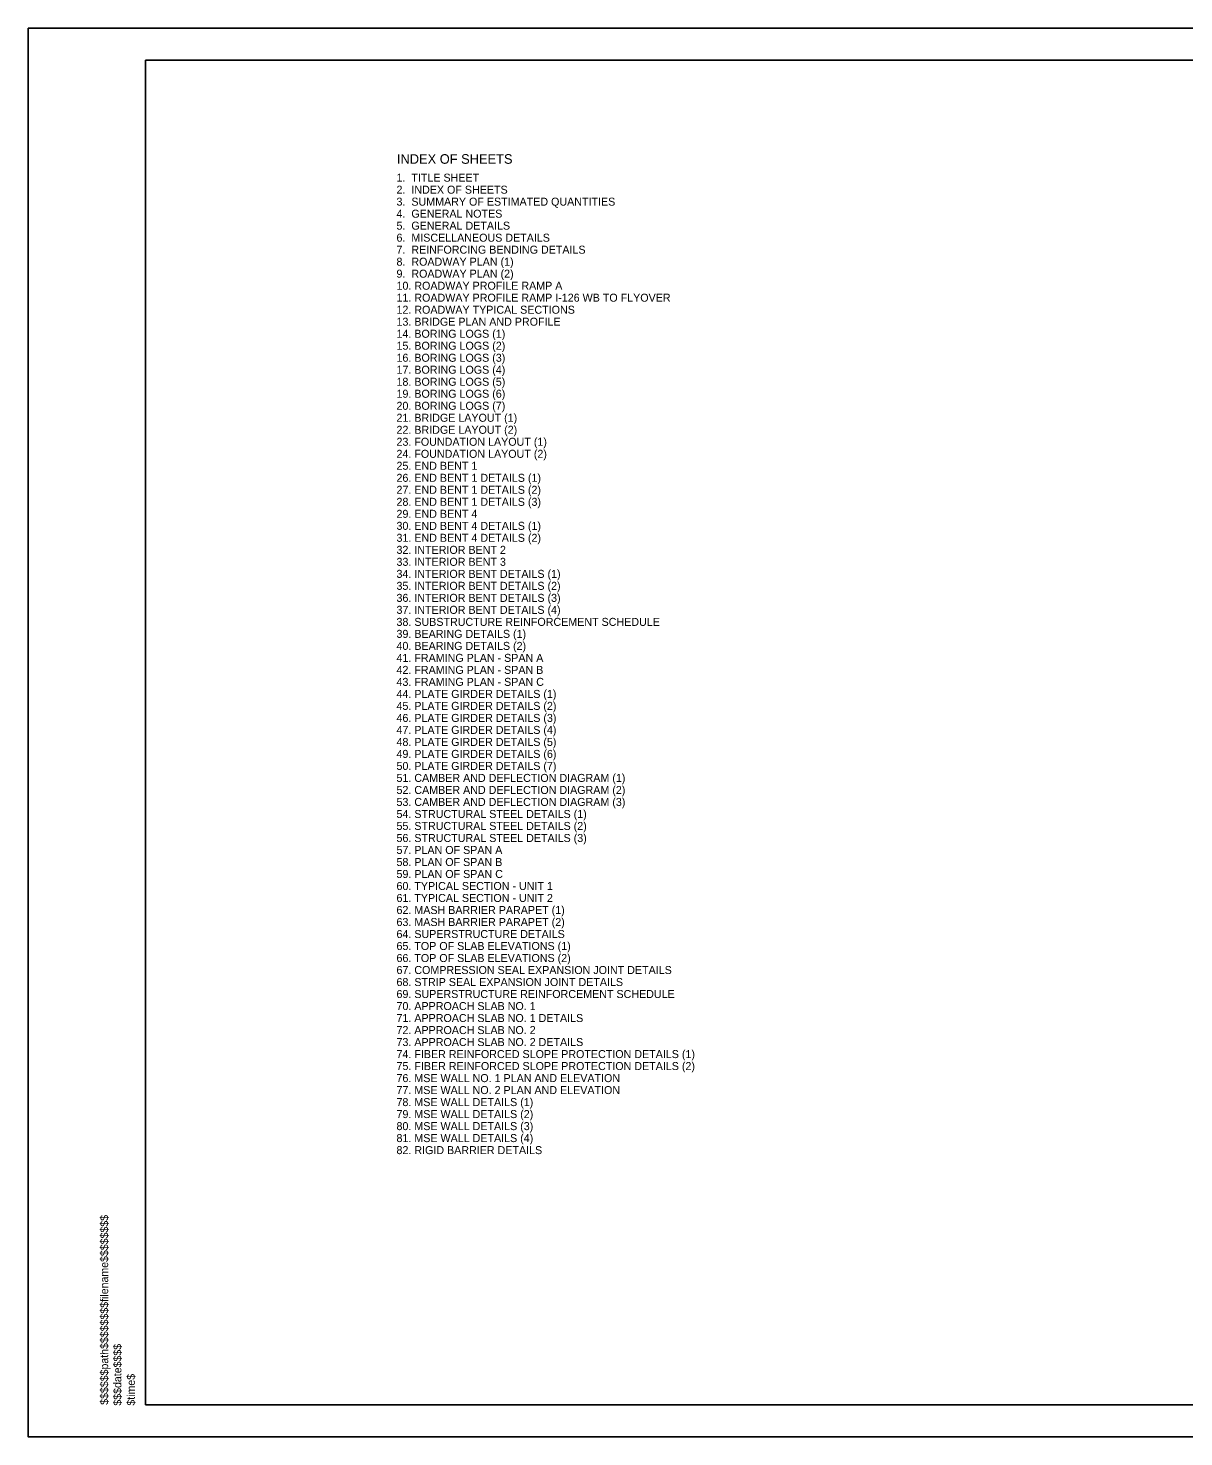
# Model space of a CAD drawing. Extents: x -125.5 to -89.4, y -5.1 to 16.9.
# Drawn here: x -125.53 to -107.48, y -5.07 to 16.93 of the extents above; entities that cross this region are included whole.
import ezdxf

# ---------------------------------------------------------------- set-up
doc = ezdxf.new("R2010")
doc.units = 0
for name, color, linetype in [('BR_AUTO DIMENSION', 7, 'Continuous'), ('BR_BORDER LINES', 7, 'Continuous'), ('BR_TEXT', 7, 'Continuous'), ('Level 31', 7, 'Continuous'), ('RD_SHT_ID', 7, 'Continuous')]:
    doc.layers.add(name, color=color, linetype=linetype)

msp = doc.modelspace()

# ---------------------------------------------------------------- linework, layer by layer
at = {"layer": 'BR_BORDER LINES'}
for p, q in [((-90.033, 16.434), (-123.699, 16.434)), ((-123.699, -4.566), (-123.699, 16.434)), ((-123.699, -4.566), (-90.033, -4.566))]:
    msp.add_line(p, q, dxfattribs=at)
at = {"layer": 'Level 31'}
msp.add_line((-89.533, 16.934), (-125.533, 16.934), dxfattribs=at)
msp.add_lwpolyline([(-125.533, 16.934), (-125.533, -5.066), (-89.533, -5.066), (-89.533, 16.934)], dxfattribs=at)

# ---------------------------------------------------------------- texts
at = {"layer": 'BR_AUTO DIMENSION'}
msp.add_text('INDEX OF SHEETS', height=0.15, dxfattribs=at).set_placement((-119.772, 14.816))
at = {"layer": 'BR_TEXT'}
for s, p in [('1.  TITLE SHEET', (-119.779, 14.537)), ('2.  INDEX OF SHEETS', (-119.779, 14.349)), ('4.  GENERAL NOTES', (-119.779, 13.974)), ('3.  SUMMARY OF ESTIMATED QUANTITIES', (-119.779, 14.162)), ('5.  GENERAL DETAILS', (-119.779, 13.787)), ('6.  MISCELLANEOUS DETAILS', (-119.779, 13.599)), ('7.  REINFORCING BENDING DETAILS  ', (-119.779, 13.412)), ('8.  ROADWAY PLAN (1)', (-119.779, 13.224)), ('9.  ROADWAY PLAN (2)', (-119.779, 13.037)), ('10. ROADWAY PROFILE RAMP A', (-119.779, 12.849)), ('11. ROADWAY PROFILE RAMP I-126 WB TO FLYOVER', (-119.779, 12.662)), ('12. ROADWAY TYPICAL SECTIONS', (-119.779, 12.474)), ('13. BRIDGE PLAN AND PROFILE', (-119.779, 12.287)), ('14. BORING LOGS (1)', (-119.779, 12.099)), ('15. BORING LOGS (2)', (-119.779, 11.912)), ('16. BORING LOGS (3)', (-119.779, 11.724)), ('17. BORING LOGS (4)', (-119.779, 11.537)), ('18. BORING LOGS (5)', (-119.779, 11.349)), ('19. BORING LOGS (6)', (-119.779, 11.162)), ('20. BORING LOGS (7)', (-119.779, 10.974)), ('21. BRIDGE LAYOUT (1)', (-119.779, 10.787)), ('22. BRIDGE LAYOUT (2)', (-119.779, 10.599)), ('23. FOUNDATION LAYOUT (1)', (-119.779, 10.412)), ('24. FOUNDATION LAYOUT (2)', (-119.779, 10.224)), ('25. END BENT 1', (-119.779, 10.037)), ('26. END BENT 1 DETAILS (1)', (-119.779, 9.849)), ('27. END BENT 1 DETAILS (2)', (-119.779, 9.662)), ('28. END BENT 1 DETAILS (3)', (-119.779, 9.474)), ('29. END BENT 4', (-119.779, 9.287)), ('30. END BENT 4 DETAILS (1)', (-119.779, 9.099)), ('31. END BENT 4 DETAILS (2)', (-119.779, 8.912)), ('32. INTERIOR BENT 2', (-119.779, 8.724)), ('33. INTERIOR BENT 3', (-119.779, 8.537)), ('34. INTERIOR BENT DETAILS (1)', (-119.779, 8.349)), ('35. INTERIOR BENT DETAILS (2)', (-119.779, 8.162)), ('36. INTERIOR BENT DETAILS (3)', (-119.779, 7.974)), ('37. INTERIOR BENT DETAILS (4)', (-119.779, 7.787)), ('38. SUBSTRUCTURE REINFORCEMENT SCHEDULE', (-119.779, 7.599)), ('39. BEARING DETAILS (1)', (-119.779, 7.412)), ('40. BEARING DETAILS (2)', (-119.779, 7.224)), ('41. FRAMING PLAN - SPAN A', (-119.779, 7.037)), ('42. FRAMING PLAN - SPAN B', (-119.779, 6.849)), ('43. FRAMING PLAN - SPAN C', (-119.779, 6.662)), ('44. PLATE GIRDER DETAILS (1) ', (-119.779, 6.474)), ('45. PLATE GIRDER DETAILS (2)', (-119.779, 6.287)), ('46. PLATE GIRDER DETAILS (3) ', (-119.779, 6.099)), ('47. PLATE GIRDER DETAILS (4)', (-119.779, 5.912)), ('48. PLATE GIRDER DETAILS (5) ', (-119.779, 5.724)), ('49. PLATE GIRDER DETAILS (6)', (-119.779, 5.537)), ('50. PLATE GIRDER DETAILS (7) ', (-119.779, 5.349)), ('51. CAMBER AND DEFLECTION DIAGRAM (1)', (-119.779, 5.162)), ('52. CAMBER AND DEFLECTION DIAGRAM (2)', (-119.779, 4.974)), ('53. CAMBER AND DEFLECTION DIAGRAM (3)', (-119.779, 4.787)), ('54. STRUCTURAL STEEL DETAILS (1)', (-119.779, 4.599)), ('55. STRUCTURAL STEEL DETAILS (2)', (-119.779, 4.412)), ('56. STRUCTURAL STEEL DETAILS (3)', (-119.779, 4.224)), ('57. PLAN OF SPAN A', (-119.779, 4.037)), ('58. PLAN OF SPAN B', (-119.779, 3.849)), ('59. PLAN OF SPAN C', (-119.779, 3.662)), ('60. TYPICAL SECTION - UNIT 1', (-119.779, 3.474)), ('61. TYPICAL SECTION - UNIT 2', (-119.779, 3.287)), ('62. MASH BARRIER PARAPET (1)', (-119.779, 3.099)), ('63. MASH BARRIER PARAPET (2)', (-119.779, 2.912)), ('64. SUPERSTRUCTURE DETAILS', (-119.779, 2.724)), ('65. TOP OF SLAB ELEVATIONS (1)', (-119.779, 2.537)), ('66. TOP OF SLAB ELEVATIONS (2)', (-119.779, 2.349)), ('67. COMPRESSION SEAL EXPANSION JOINT DETAILS', (-119.779, 2.162)), ('68. STRIP SEAL EXPANSION JOINT DETAILS', (-119.779, 1.974)), ('69. SUPERSTRUCTURE REINFORCEMENT SCHEDULE', (-119.779, 1.787)), ('70. APPROACH SLAB NO. 1', (-119.779, 1.599)), ('71. APPROACH SLAB NO. 1 DETAILS', (-119.779, 1.412)), ('72. APPROACH SLAB NO. 2', (-119.779, 1.224)), ('73. APPROACH SLAB NO. 2 DETAILS', (-119.779, 1.037)), ('74. FIBER REINFORCED SLOPE PROTECTION DETAILS (1)', (-119.779, 0.849)), ('75. FIBER REINFORCED SLOPE PROTECTION DETAILS (2)', (-119.779, 0.662)), ('76. MSE WALL NO. 1 PLAN AND ELEVATION', (-119.779, 0.474)), ('77. MSE WALL NO. 2 PLAN AND ELEVATION', (-119.779, 0.287)), ('78. MSE WALL DETAILS (1)', (-119.779, 0.099)), ('79. MSE WALL DETAILS (2)', (-119.779, -0.088)), ('80. MSE WALL DETAILS (3)', (-119.779, -0.276)), ('81. MSE WALL DETAILS (4)', (-119.779, -0.463)), ('82. RIGID BARRIER DETAILS', (-119.779, -0.651))]:
    msp.add_text(s, height=0.125, dxfattribs=at).set_placement(p)
at = {"layer": 'RD_SHT_ID'}
for s, height, p in [('$$$$$$path$$$$$$$$filename$$$$$$$$', 0.12347, (-124.283, -4.566)), ('$$$date$$$$', 0.12347, (-124.077, -4.579)), ('$time$', 0.1235, (-123.866, -4.579))]:
    msp.add_text(s, height=height, rotation=90, dxfattribs=at).set_placement(p)

doc.saveas('drawing.dxf')
